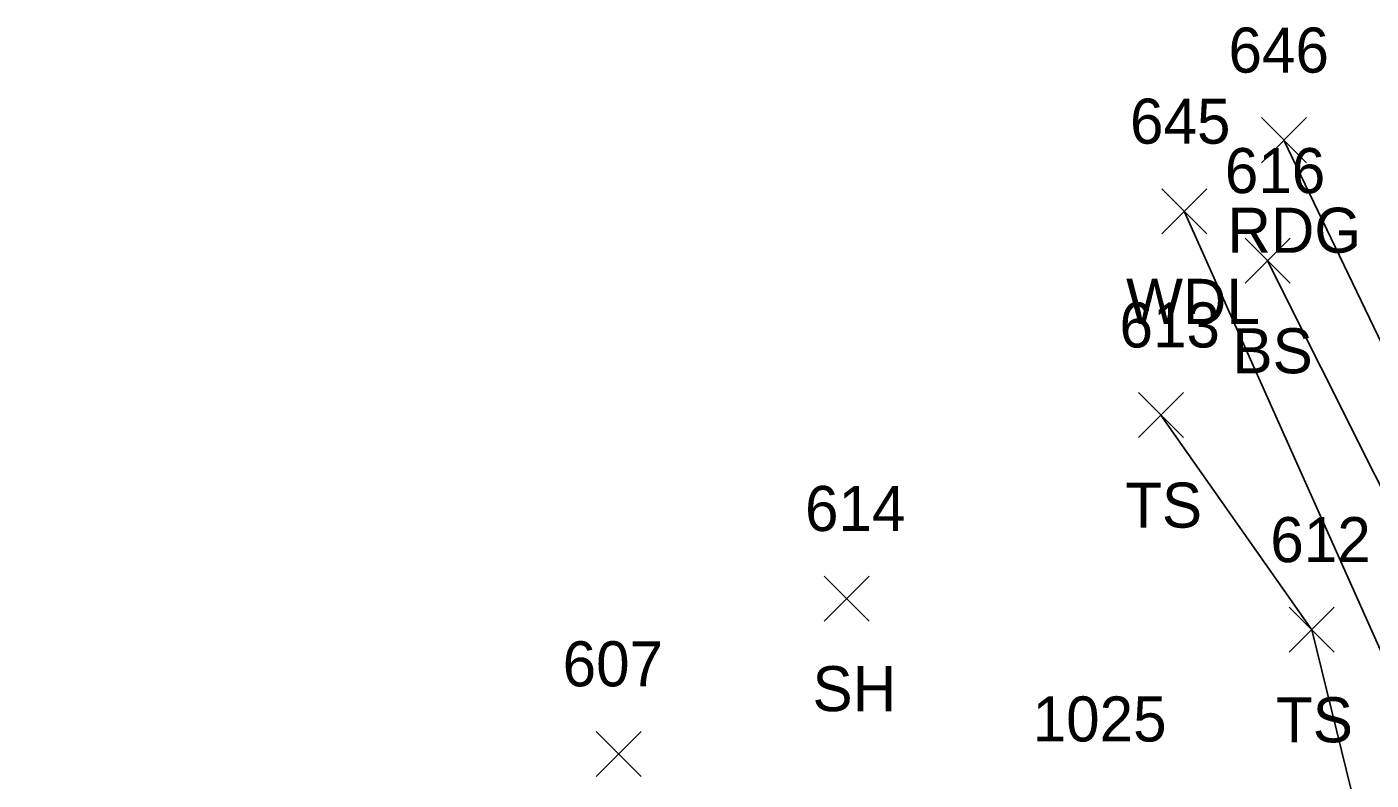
# Model space of a CAD drawing. Extents: x 1528286 to 1556263, y 492387 to 508952.
# Drawn here: x 1528408.9 to 1528468.6, y 492693.2 to 492726.6 of the extents above; entities that cross this region are included whole.
import ezdxf

# ---------------------------------------------------------------- set-up
doc = ezdxf.new("R2010")
doc.units = 0
for name, color, linetype in [('C_I', 7, 'Continuous'), ('L_A', 7, 'Continuous'), ('L_I', 7, 'Continuous'), ('L_TIC', 7, 'Continuous'), ('LAWA', 7, 'Continuous'), ('LELB', 7, 'Continuous'), ('P_A', 7, 'Continuous'), ('P_I', 7, 'Continuous'), ('P_TIC', 7, 'Continuous'), ('PEU', 7, 'Continuous')]:
    doc.layers.add(name, color=color, linetype=linetype)

msp = doc.modelspace()

# ---------------------------------------------------------------- linework, layer by layer
at = {"layer": 'L_TIC'}
for points in [[(1528459.273, 492717.435), (1528461.273, 492719.435)], [(1528461.273, 492717.435), (1528459.273, 492719.435)], [(1528459.273, 492717.435), (1528461.273, 492719.435)], [(1528461.273, 492717.435), (1528459.273, 492719.435)], [(1528462.974, 492715.24), (1528464.974, 492717.24)], [(1528464.974, 492715.24), (1528462.974, 492717.24)], [(1528462.974, 492715.24), (1528464.974, 492717.24)], [(1528464.974, 492715.24), (1528462.974, 492717.24)], [(1528458.238, 492708.386), (1528460.238, 492710.386)], [(1528460.238, 492708.386), (1528458.238, 492710.386)], [(1528458.238, 492708.386), (1528460.238, 492710.386)], [(1528460.238, 492708.386), (1528458.238, 492710.386)], [(1528444.27, 492700.236), (1528446.27, 492702.236)], [(1528446.27, 492700.236), (1528444.27, 492702.236)], [(1528444.27, 492700.236), (1528446.27, 492702.236)], [(1528446.27, 492700.236), (1528444.27, 492702.236)], [(1528464.938, 492698.853), (1528466.938, 492700.853)], [(1528466.938, 492698.853), (1528464.938, 492700.853)], [(1528464.938, 492698.853), (1528466.938, 492700.853)], [(1528466.938, 492698.853), (1528464.938, 492700.853)], [(1528434.148, 492693.339), (1528436.148, 492695.339)], [(1528436.148, 492693.339), (1528434.148, 492695.339)], [(1528434.148, 492693.339), (1528436.148, 492695.339)], [(1528436.148, 492693.339), (1528434.148, 492695.339)]]:
    msp.add_lwpolyline(points, dxfattribs=at)
at = {"layer": 'LAWA'}
msp.add_lwpolyline([(1528305.143, 492527.842), (1528342.933, 492565.336), (1528378.694, 492601.441), (1528416.012, 492639), (1528453.009, 492673.153), (1528472.803, 492690.435), (1528460.273, 492718.435)], dxfattribs=at)
msp.add_lwpolyline([(1528305.143, 492527.842), (1528342.933, 492565.336), (1528378.694, 492601.441), (1528416.012, 492639), (1528453.009, 492673.153), (1528472.803, 492690.435), (1528460.273, 492718.435)], dxfattribs=at)
at = {"layer": 'LELB'}
for points in [[(1528463.974, 492716.24), (1528473.5, 492697.234), (1528475.042, 492686.518), (1528472.395, 492681.69), (1528457.302, 492666.687)], [(1528463.974, 492716.24), (1528473.5, 492697.234), (1528475.042, 492686.518), (1528472.395, 492681.69), (1528457.302, 492666.687)], [(1528439.397, 492683.965), (1528447.056, 492673.146), (1528454.655, 492669.581), (1528469.663, 492684.737), (1528465.938, 492699.853), (1528459.238, 492709.386)], [(1528439.397, 492683.965), (1528447.056, 492673.146), (1528454.655, 492669.581), (1528469.663, 492684.737), (1528465.938, 492699.853), (1528459.238, 492709.386)]]:
    msp.add_lwpolyline(points, dxfattribs=at)
at = {"layer": 'P_TIC'}
for points in [[(1528463.703, 492720.592), (1528465.703, 492722.592)], [(1528465.703, 492720.592), (1528463.703, 492722.592)], [(1528463.703, 492720.592), (1528465.703, 492722.592)], [(1528465.703, 492720.592), (1528463.703, 492722.592)]]:
    msp.add_lwpolyline(points, dxfattribs=at)
at = {"layer": 'PEU'}
msp.add_lwpolyline([(1528464.703, 492721.592), (1528476.134, 492697.856), (1528480.12, 492689.363), (1528484.355, 492676.123)], dxfattribs=at)
msp.add_lwpolyline([(1528464.703, 492721.592), (1528476.134, 492697.856), (1528480.12, 492689.363), (1528484.355, 492676.123)], dxfattribs=at)

# ---------------------------------------------------------------- texts
at = {"layer": 'C_I'}
msp.add_text('1025', height=2, dxfattribs=at).set_placement((1528453.539, 492694.89))
msp.add_text('1025', height=2, dxfattribs=at).set_placement((1528453.539, 492694.89))
at = {"layer": 'L_A'}
for s, p in [('WDL', (1528457.69, 492713.435)), ('WDL', (1528457.69, 492713.435)), ('BS', (1528462.414, 492711.24)), ('BS', (1528462.414, 492711.24)), ('TS', (1528457.648, 492704.386)), ('TS', (1528457.648, 492704.386)), ('SH', (1528443.758, 492696.236)), ('SH', (1528443.758, 492696.236)), ('TS', (1528464.348, 492694.853)), ('TS', (1528464.348, 492694.853))]:
    msp.add_text(s, height=2, dxfattribs=at).set_placement(p)
at = {"layer": 'L_I'}
for s, p in [('645', (1528457.863, 492721.435)), ('645', (1528457.863, 492721.435)), ('616', (1528462.076, 492719.24)), ('616', (1528462.076, 492719.24)), ('613', (1528457.396, 492712.386)), ('613', (1528457.396, 492712.386)), ('614', (1528443.428, 492704.236)), ('614', (1528443.428, 492704.236)), ('612', (1528464.096, 492702.853)), ('612', (1528464.096, 492702.853)), ('607', (1528432.66, 492697.339)), ('607', (1528432.66, 492697.339))]:
    msp.add_text(s, height=2, dxfattribs=at).set_placement(p)
at = {"layer": 'P_A'}
msp.add_text('RDG', height=2, dxfattribs=at).set_placement((1528462.191, 492716.592))
msp.add_text('RDG', height=2, dxfattribs=at).set_placement((1528462.191, 492716.592))
at = {"layer": 'P_I'}
msp.add_text('646', height=2, dxfattribs=at).set_placement((1528462.239, 492724.592))
msp.add_text('646', height=2, dxfattribs=at).set_placement((1528462.239, 492724.592))

doc.saveas('drawing.dxf')
